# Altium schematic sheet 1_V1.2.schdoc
size 309 x 223 mm; Symbol: Sheet-Symbol_A4; Device: Sheet-Symbol_A4; @Page Name: V1.2; @Create Date: 2022-08-15; @Page Count: 1; @Page No: 1; @Project Name: Spark_T12; @Schematic Name: Schematic1; @Update Date: 2022-10-22; Drawed: 信电二班小皮同学; Page Size: A4; Reviewed: 信电二班小皮同学; Version: V1.0; Convert to PCB: yes; Add into BOM: yes
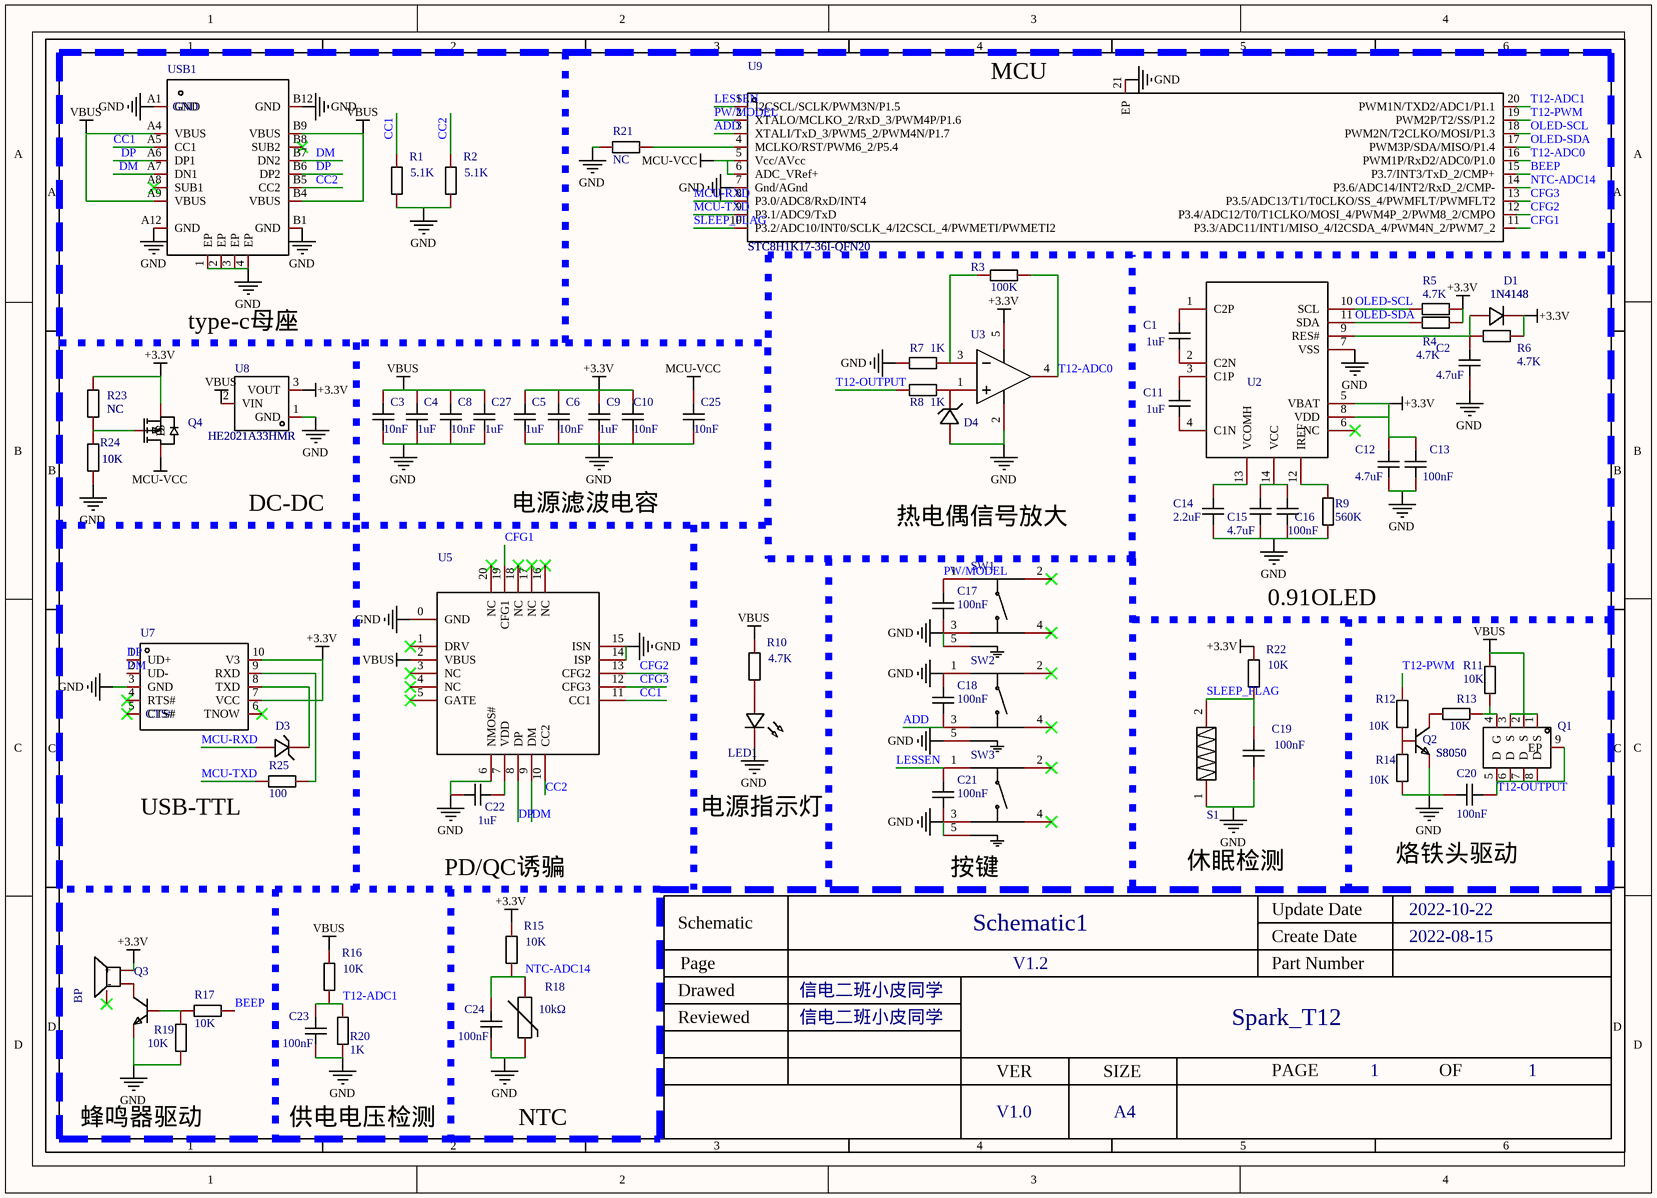
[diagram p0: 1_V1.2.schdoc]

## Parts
BP  MLT-5020  [BUZ-SMD_3P-L5.2-W5.2-P3.50-BR]  (value not drawn)
C1  value 1uF  (hidden comment: CAP_0402)
C2  value 4.7uF  (hidden comment: CAP_0402)
C3  value 10nF  (hidden comment: CAP_0402)
C4  value 1uF  (hidden comment: CAP_0402)
C5  value 1uF  (hidden comment: CAP_0402)
C6  value 10nF  (hidden comment: CAP_0402)
C8  value 10nF  (hidden comment: CAP_0402)
C9  value 1uF  (hidden comment: CAP_0402)
C10  value 10nF  (hidden comment: CAP_0402)
C11  value 1uF  (hidden comment: CAP_0402)
C12  value 4.7uF  (hidden comment: CAP_0402)
C13  value 100nF  (hidden comment: CAP_0402)
C14  value 2.2uF  (hidden comment: CAP_0402)
C15  value 4.7uF  (hidden comment: CAP_0402)
C16  value 100nF  (hidden comment: CAP_0402)
C17  value 100nF  (hidden comment: CAP_0402)
C18  value 100nF  (hidden comment: CAP_0402)
C19  value 100nF  (hidden comment: CAP_0402)
C20  value 100nF  (hidden comment: CAP_0402)
C21  value 100nF  (hidden comment: CAP_0402)
C22  value 1uF  (hidden comment: CAP_0402)
C23  value 100nF  (hidden comment: CAP_0402)
C24  value 100nF  (hidden comment: CAP_0402)
C25  value 10nF  (hidden comment: CAP_0402)
C27  value 1uF  (hidden comment: CAP_0402)
D1  1N4148  [SOD-523_L1.2-W0.8-LS1.6-RD]
D3  1N4148WS  [SOD-323_L1.6-W1.3-LS2.6-RD]  (value not drawn)
D4  BZX584C3V3  [SOD-523F_L1.2-W0.8-LS1.7-RD]  (value not drawn)
LED1  LED_0603-R  [LED0603-RD_BLUE]  (value not drawn)
Q1  SE30P12D  [DFN-8_L3.0-W3.0-P0.65-BL]  (value not drawn)
Q2  S8050  [SOT-23_L2.9-W1.3-P1.90-LS2.4-BR]
Q3  S8050_NPN  [SOT-23_L2.9-W1.3-P1.90-LS2.4-BR]  (value not drawn)
Q4  AO3401A_P  [SOT-23_L2.9-W1.3-P1.90-LS2.4-BR]  (value not drawn)
R1  value 5.1K  [R0603]  (hidden comment: Res_0402)
R2  value 5.1K  [R0603]  (hidden comment: Res_0402)
R3  value 100K  [R0603]  (hidden comment: Res_0402)
R4  value 4.7K  [R0603]  (hidden comment: Res_0402)
R5  value 4.7K  [R0603]  (hidden comment: Res_0402)
R6  value 4.7K  [R0603]  (hidden comment: Res_0402)
R7  value 1K  [R0603]  (hidden comment: Res_0402)
R8  value 1K  [R0603]  (hidden comment: Res_0402)
R9  value 560K  [R0603]  (hidden comment: Res_0402)
R10  value 4.7K  [R0603]  (hidden comment: Res_0402)
R11  value 10K  [R0603]  (hidden comment: Res_0402)
R12  value 10K  [R0603]  (hidden comment: Res_0402)
R13  value 10K  [R0603]  (hidden comment: Res_0402)
R14  value 10K  [R0603]  (hidden comment: Res_0402)
R15  value 10K  [R0603]  (hidden comment: Res_0402)
R16  value 10K  [R0603]  (hidden comment: Res_0402)
R17  value 10K  [R0603]  (hidden comment: Res_0402)
R18  Resistance @ 25℃: 10kΩ  [R0402]  (hidden comment: B57221V2103J060)
R19  value 10K  [R0603]  (hidden comment: Res_0402)
R20  value 1K  [R0603]  (hidden comment: Res_0402)
R21  Res_0402  [R0603]  (value not drawn)
R22  value 10K  [R0603]  (hidden comment: Res_0402)
R23  NC  [R0603]
R24  10K  [R0603]
R25  value 100  [R0603]  (hidden comment: Res_0402)
S1  BL-2030  [SMD-Pan1.5*0.8-2P-S2.8]  (value not drawn)
SW1  TS3315A  [SW-SMD_4P-L3.4-W3.4-P2.00-LS4.0_TS3315A160GF]  (value not drawn)
SW2  TS3315A  [SW-SMD_4P-L3.4-W3.4-P2.00-LS4.0_TS3315A160GF]  (value not drawn)
SW3  TS3315A  [SW-SMD_4P-L3.4-W3.4-P2.00-LS4.0_TS3315A160GF]  (value not drawn)
U2  SSD1306-14Pin_0.91_JX  (value not drawn)
U3  LM321MFX  [SOT-23-5_L2.9-W1.6-P0.95-LS2.8-BL]  (value not drawn)
U5  CH224D  [QFN20_3X3]  (value not drawn)
U7  NAME: CTS#  [MSOP-10_L3.0-W3.0-P0.50-LS5.0-BL]  (hidden comment: CH340E)
U8  HE2021A33HMR  [SOT-23-3_L2.9-W1.6-P1.90-LS2.8-BR-CW]
U9  STC8H1K17-36I-QFN20  [QFN-20_L3.0-W3.0-P0.40-BL-EP1.7]
USB1  NAME: GND  [USB-C-SMD_KH-TYPE-C-16P]  (hidden comment: KH-TYPE-C-16P)

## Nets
+3.3V: BP.2(+) C5.2 C6.2 C9.2 C10.2 C12.2 C13.2 D1.2(C) Q4.2(S) R4.2 R5.2 R6.2 R15.2 R22.2 R23.2 U2.5(VBAT) U2.8(VDD) U3.5(+VS) U7.7(VCC) U7.10(V3) U8.3(VOUT)
GND: C2.1 C3.1 C4.1 C5.1 C6.1 C8.1 C9.1 C10.1 C12.1 C13.1 C14.1 C15.1 C16.1 C17.1 C18.2 C19.1 C20.1 C21.1 C22.2 C23.1 C24.1 C25.1 C27.1 D4.2(A) LED1.1(C) Q2.2(E) Q3.2(E) R1.1 R2.1 R7.1 R9.1 R14.1 R18.1 R19.1 R20.1 R21.1 R24.1 S1.1(Pin1) SW1.3(C) SW1.5(GND) SW2.1(A) SW2.5(GND) SW3.3(C) SW3.5(GND) U2.7(VSS) U3.2(-VS) U5.0(GND) U5.6(NMOS#) U5.14(ISP) U5.15(ISN) U7.3(GND) U8.1(GND) U9.7(Gnd/AGnd) U9.21(EP) USB1.1(EP) USB1.2(EP) USB1.3(EP) USB1.4(EP) USB1.A1(GND) USB1.A12(GND) USB1.B1(GND) USB1.B12(GND)
MCU-VCC: C25.2 Q4.3(D) U9.5(Vcc/AVcc) U9.6(ADC_VRef+)
VBUS: C3.2 C4.2 C8.2 C27.2 Q1.1(S) Q1.2(S) Q1.3(S) R10.2 R11.2 R16.2 U5.2(VBUS) U8.2(VIN) USB1.A4(VBUS) USB1.A9(VBUS) USB1.B4(VBUS) USB1.B9(VBUS)
ADD: C18.1 SW2.3(C) U9.3(XTALI/TxD_3/PWM5_2/PWM4N/P1.7)
BEEP: R17.1 U9.15(P3.7/INT3/TxD_2/CMP+)
CC1: R1.2 U5.11(CC1) USB1.A5(CC1)
CC2: R2.2 U5.10(CC2) USB1.B5(CC2)
CFG1: U5.19(CFG1) U9.11(P3.3/ADC11/INT1/MISO_4/I2CSDA_4/PWM4N_2/PWM7_2)
CFG2: U5.13(CFG2) U9.12(P3.4/ADC12/T0/T1CLKO/MOSI_4/PWM4P_2/PWM8_2/CMPO)
CFG3: U5.12(CFG3) U9.13(P3.5/ADC13/T1/T0CLKO/SS_4/PWMFLT/PWMFLT2)
DM: U5.9(DM) U7.2(UD-) USB1.A7(DN1) USB1.B7(DN2)
DP: U5.8(DP) U7.1(UD+) USB1.A6(DP1) USB1.B6(DP2)
LESSEN: C21.2 SW3.1(A) U9.1(I2CSCL/SCLK/PWM3N/P1.5)
MCU-RXD: D3.2(A) U9.8(P3.0/ADC8/RxD/INT4)
MCU-TXD: R25.1 U9.9(P3.1/ADC9/TxD)
NTC-ADC14: C24.2 R15.1 R18.2 U9.14(P3.6/ADC14/INT2/RxD_2/CMP-)
OLED-SCL: R5.1 U2.10(SCL) U9.18(PWM2N/T2CLKO/MOSI/P1.3)
OLED-SDA: R4.1 U2.11(SDA) U9.17(PWM3P/SDA/MISO/P1.4)
PW/MODEL: C17.2 SW1.1(A) U9.2(XTALO/MCLKO_2/RxD_3/PWM4P/P1.6)
SLEEP_FLAG: C19.2 R22.1 S1.2(Pin2) U9.10(P3.2/ADC10/INT0/SCLK_4/I2CSCL_4/PWMETI/PWMETI2)
T12-ADC0: R3.2 U3.4(OUT) U9.16(PWM1P/RxD2/ADC0/P1.0)
T12-ADC1: C23.2 R16.1 R20.2 U9.20(PWM1N/TXD2/ADC1/P1.1)
T12-OUTPUT: C20.2 Q1.5(D) Q1.6(D) Q1.7(D) Q1.8(D) Q1.9(EP) R8.1
T12-PWM: R12.2 U9.19(PWM2P/T2/SS/P1.2)
NetBP_3: BP.3(-) Q3.3(C)
NetC1_1: C1.1 U2.2(C2N)
NetC1_2: C1.2 U2.1(C2P)
NetC2_2: C2.2 D1.1(A) R6.1 U2.9(RES#)
NetC11_1: C11.1 U2.4(C1N)
NetC11_2: C11.2 U2.3(C1P)
NetC14_2: C14.2 U2.13(VCOMH)
NetC15_2: C15.2 C16.2 U2.14(VCC)
NetC22_1: C22.1 U5.7(VDD)
NetD3_1: D3.1(C) U7.8(TXD)
NetD4_1: D4.1(K) R8.2 U3.1(+IN)
NetLED1_2: LED1.2(A) R10.1
NetQ1_4: Q1.4(G) R11.1 R13.2
NetQ2_1: Q2.1(B) R12.1 R14.2
NetQ2_3: Q2.3(C) R13.1
NetQ3_1: Q3.1(B) R17.2 R19.2
NetQ4_1: Q4.1(G) R23.1 R24.2
NetR3_1: R3.1 R7.2 U3.3(-IN)
NetR9_2: R9.2 U2.12(IREF)
NetR21_2: R21.2 U9.4(MCLKO/RST/PWM6_2/P5.4)
NetR25_2: R25.2 U7.9(RXD)

Not connected (* = marked no-connect by the designer): BP 1(NC)*; SW1 2(B)* 4(D)*; SW2 2(B)* 4(D)*; SW3 2(B)* 4(D)*; U2 6(NC)*; U5 1(DRV)* 3(NC)* 4(NC)* 5(GATE)* 16(NC)* 17(NC)* 18(NC)* 20(NC)*; U7 4(RTS#)* 5(CTS#)* 6(TNOW)*; USB1 A8(SUB1)* B8(SUB2)*

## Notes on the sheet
- (near U9) MCU
- type-c母座
- DC-DC
- 电源滤波电容
- 热电偶信号放大
- 0.91OLED
- USB-TTL
- 电源指示灯
- PD/QC诱骗
- (near SW3) 按键
- 休眠检测
- 烙铁头驱动
- 蜂鸣器驱动
- 供电电压检测
- NTC

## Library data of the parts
BP = MLT-5020: 驱动方式:无源(外部驱动);构造类型:电磁式;频率:4000Hz;长度:5.2mm;宽度:5.2mm;高度:2.5mm;; Manufacturer: 华能; Add into BOM: yes; Technology Type: 电磁式; Value: 4000Hz
C1-C6 C8-C12 C15 C25 C27 = CAP_0402: Symbol: C1210X7R475K630NT; Convert to PCB: yes; Description: 容值:100nF;精度:±10%;额定电压:16V;温度系数:X7R;
C13 C14 C16-C24 = CAP_0402: 容值:100nF;精度:±10%;额定电压:16V;温度系数:X7R;; Symbol: C1210X7R475K630NT; Convert to PCB: yes
D1 = 1N4148WT: 二极管配置:独立式;功率:150mW;直流反向耐压(Vr):75V;平均整流电流(Io):150mA;正向压降(Vf):1.25V@150mA;反向电流(Ir):1A@75V;反向恢复时间(trr):4ns;工作温度:+150@(Tj);; Manufacturer: SMC(桑德斯); Symbol: 1N4148WT_C493211; Add into BOM: yes; Diode Configuration: 独立式; Power Dissipation: 150mW; Reverse Voltage (Vr): 75V; Average Rectified Current (Io): 150mA; Reverse Leakage Current: 1A@75V; Reverse Recovery Time (trr): 4ns
D3 = 1N4148WS_C1884546: 二极管配置:独立式;功率:400mW;直流反向耐压(Vr):100V;平均整流电流(Io):200mA;正向压降(Vf):1.25V@150mA;反向电流(Ir):1A@75V;反向恢复时间(trr):4ns;工作温度:-55~+150@(Tj);; Manufacturer: YFW佑风微; Add into BOM: yes; Diode Configuration: 独立式; Power Dissipation: 400mW; Reverse Voltage (Vr): 100V; Average Rectified Current (Io): 200mA; Reverse Leakage Current: 1A@75V; Reverse Recovery Time (trr): 4ns
D4 = BZX584C3V3: Manufacturer: VISHAY; Manufacturer Part: BZX584C2V4-V-G-08; Add into BOM: yes
LED1 = LED_0603-R: 发光颜色:红灯;二极管配置:-;透镜颜色:无色透明;主波长:617.5nm;峰值波长:632nm;色温:-;光通量(25时):-;测试电流:5mA;正向电压(VF):2.2V;发光强度:28.5mcd;功率:60mW;发光角度:120°;安装方式:-;工作温度:-40~+85;; Symbol: LED_R; Convert to PCB: yes
Q1 = SE30P12D: 类型:P沟道;漏源电压(Vdss):30V;连续漏极电流(Id):12A;功率(Pd):2W;导通电阻(RDS(on)@Vgs,Id):15mΩ@10V,10A;阈值电压(Vgs(th)@Id):3V@250uA;; Manufacturer: SINO-IC(光宇睿芯); Add into BOM: yes; Type: P沟道; Drain Source Voltage (Vdss): 30V; Continuous Drain Current (Id): 12A; Power Dissipation (Pd): 2W
Q2 Q3 = S8050_NPN: 晶体管类型:NPN;集射极击穿电压(Vceo):25V;集电极电流(Ic):500mA;功率(Pd):300mW;集电极-发射极饱和电压(VCE(sat)@Ic,Ib):600mV@500mA,50mA;直流电流增益(hFE@Ic,Vce):-;特征频率(fT):150MHz;工作温度:+150@(Tj);; Symbol: NPN; Convert to PCB: yes
Q4 = AO3401A_P: 类型:P沟道;漏源电压(Vdss):30V;连续漏极电流(Id):4A;功率(Pd):1.4W;导通电阻(RDS(on)@Vgs,Id):44mΩ@10V,4.3A;阈值电压(Vgs(th)@Id):1.3V@250A;; Symbol: P_MOS; Add into BOM: yes
R1-R17 R19 R20 R22 R24 R25 = Res_0402: Symbol: 电阻; Convert to PCB: yes
R18 = B57221V2103J060: 阻值(25):10kΩ;电阻精度:±5%;B值精度:±3%;B值(25/50):3940K;功率:150mW;最大稳态电流(25):-;B值(25/75):-;B值(25/85):3980K;B值(25/100):4000K;工作温度:-;; Manufacturer: TDK; Add into BOM: yes; Resistance Tolerance: ±5%; B Constant Tolerance: ±3%; B Constant (25℃/50℃): 3940K; Power: 150mW; B Constant (25℃/85℃): 3980K; B Constant (25℃/100℃): 4000K
R21 = Res_0402: NC; Symbol: 电阻; Convert to PCB: yes; Value: 10K
R23 = Res_0603: Symbol: 电阻; Convert to PCB: yes
S1 = BL-2030: 百灵电子BL2030 体积最小型震动传感器贴片振动开关（链接：https://item.taobao.com/item.htm?spm=a1z10.5-c-s.w4002-22402150702.17.63496d28pZ4dAa&id=546239839707）; Symbol: BL2030; Convert to PCB: yes
SW1-SW3 = TS3315A: 触点电流:50mA;额定电压(AC):-;额定电压(DC):12V;额定功率:-;绝缘电阻:-;电路结构:单刀单掷;安装方式:立贴;按钮形状:圆形按钮;按钮/盖帽颜色:-;带灯:-;作用力:5N;机械寿命:-;工作温度:-;防护等级:-;引脚样式:-;开关长度:3.3mm;开关宽度:3.3mm;开关高度:1.5mm;带支架:-;; Manufacturer: SHOU HAN(首韩); Add into BOM: yes; Contact Current: 50mA; Voltage Rating (DC): 12V; Circuit: 单刀单掷; Actuator Style: 圆形按钮; Operating Force: 5N; Switch Length: 3.3mm; Switch Height: 1.5mm
U2 = SSD1306-14Pin_0.91_JX: Add into BOM: yes
U3 = LM321MFX: Manufacturer: TECH PUBLIC(台舟); Add into BOM: yes
U5 = CH224D: USB PD & Type-C & Fast Charge Power Consumer Controller; Add into BOM: yes
U7 = CH340E: 类型:Transceiver;协议类别:USB 2.0;驱动器/接收器数:-;数据速率:2Mbps;; Manufacturer: WCH(南京沁恒); Add into BOM: yes; Protocol: USB 2.0; Data Rate: 2Mbps; Supply Voltage: 3.3V, 5V
U8 = HE2021A33HMR: 输出类型:固定;输出极性:正;输出通道数:1;最大输入电压:35V;输出电压:3.3V;压差:400mV;静态电流(地电流):2A;输出电流:200mA;电源纹波抑制比(PRSS):60dB@1kHz;; Manufacturer: HEERMICR(赫尔半导体); Add into BOM: yes; Output Type: 固定; Output Polarity: 正; Number of Outputs: 1; Maximum Input Voltage: 35V; Output Voltage: 3.3V; Dropout Voltage: 400mV; Quiescent Current (Ground Current): 2μA; Output Current: 200mA
U9 = STC8H1K17-36I-QFN20: CPU内核:51系列;CPU最大主频:-;工作电压范围:1.9V~5.5V;内部振荡器:有;外部时钟频率范围:4MHz~33MHz;程序 FLASH容量:17KB;RAM总容量:1.25KB;EEPROM/数据 FLASH容量:-;GPIO端口数量:17;ADC(单元数/通道数/位数):1@x9ch/10bit;DAC(单元数/通道数/位数):-;(E)PWM(单元数/通道数/位数):2@x4ch/16bit;8位Timer数量:-;16位Timer数量:3;32位Timer数量:-;内部比较器数量:1;; Manufacturer: STC(宏晶); Add into BOM: yes; CPU Core: 51系列; Internal Oscillator: 有; Program FLASH Size: 17KB; RAM Size: 1.25KB; GPIO Ports Number: 17; 16Bit Timer Number: 3; CMP Number: 1; U(S)ART Number: 2; Peripherals / Functions / Protocol Stacks: 低电压检测；看门狗；CCP捕获/比较
USB1 = KH-TYPE-C-16P: 连接器类型:Type-C;标准:-;公母:母座;触点数量:16;端口数量:1;安装方式:卧贴;额定电流 - 电源:3A;工作温度范围:-40~+85;; Manufacturer: kinghelm(金航标); Add into BOM: yes; Connector Type: Type-C; Gender: 母座; Number of Contacts: 16; Number of Ports: 1; Current Rating - Power (Max): 3A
